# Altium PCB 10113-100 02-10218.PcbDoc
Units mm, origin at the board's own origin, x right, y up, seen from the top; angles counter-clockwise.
Board outline 67 x 67 mm, 2 copper layers (Top Layer, Bottom Layer); 24 components, 35 nets, 116 pads, 182 vias.
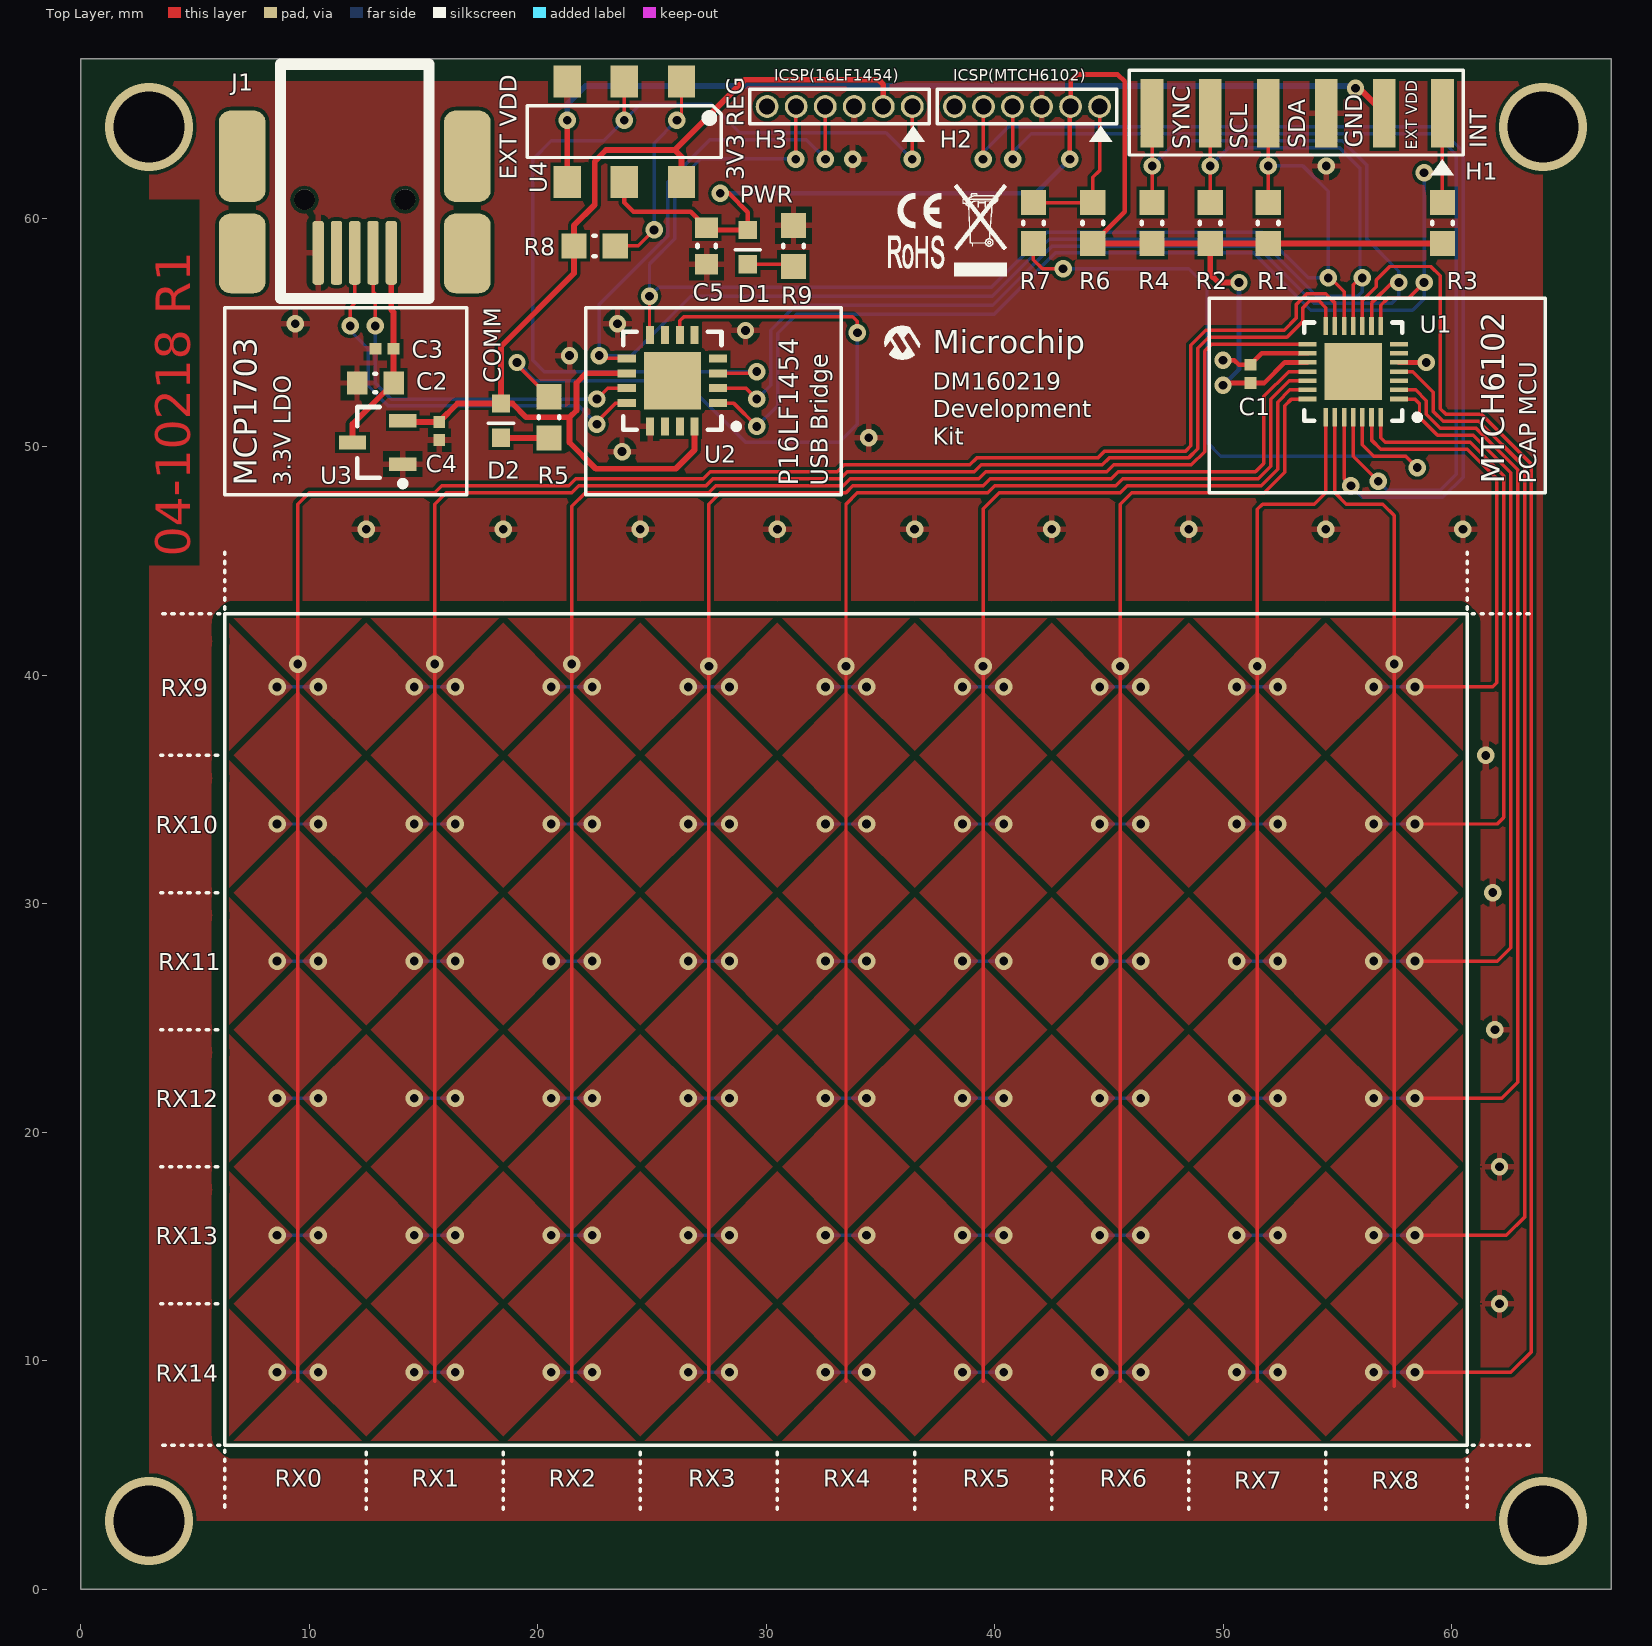
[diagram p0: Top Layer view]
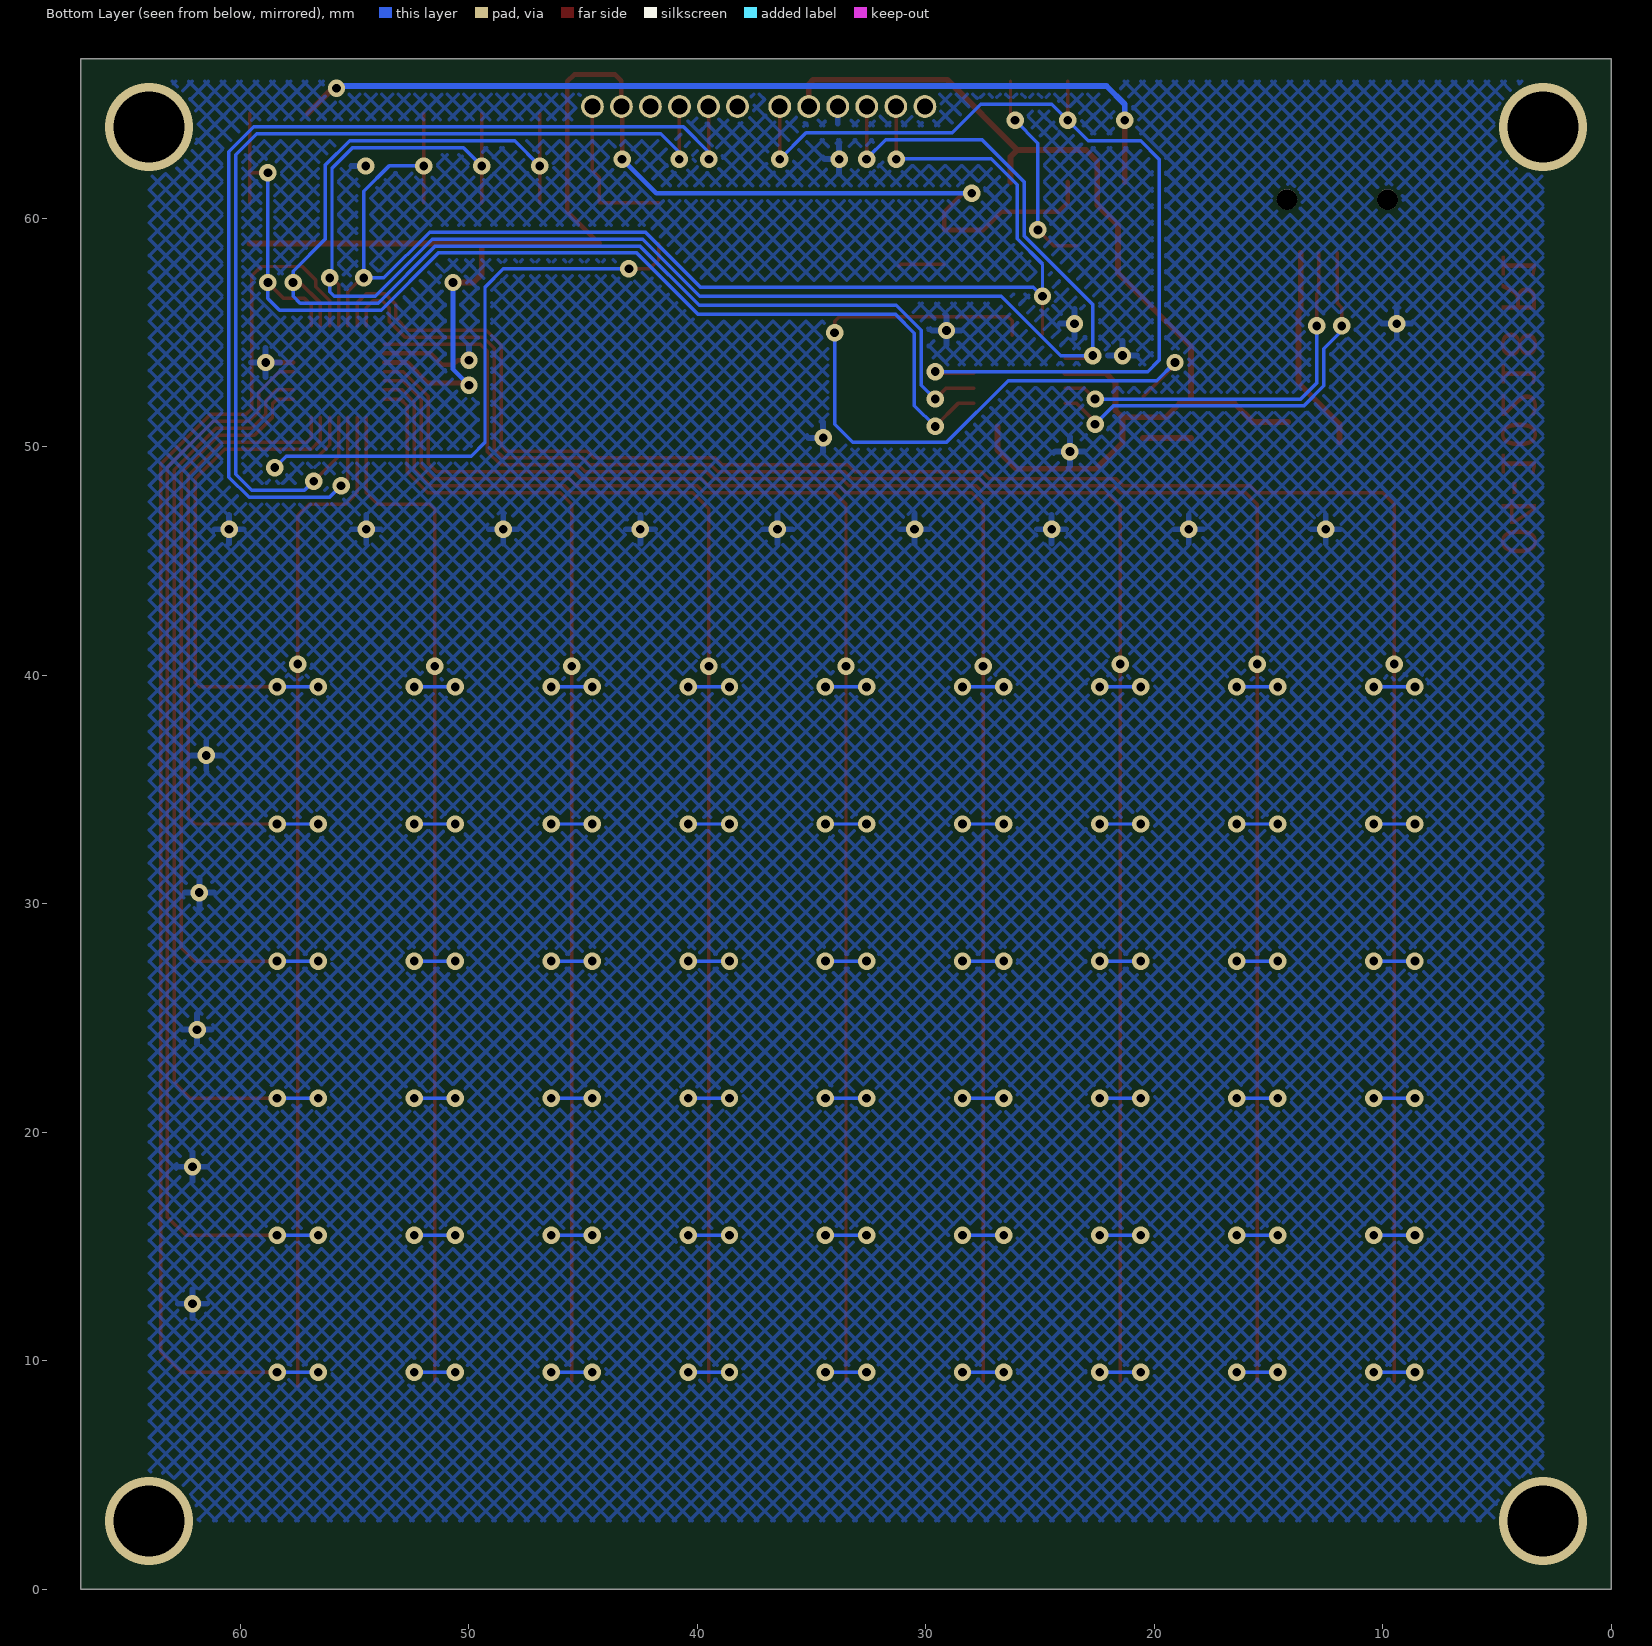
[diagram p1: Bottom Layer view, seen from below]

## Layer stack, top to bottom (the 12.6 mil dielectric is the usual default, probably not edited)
Top Solder: solder mask 0.0102, Solder Resist, Dk 3.5
Top Layer: signal copper 0.0356
Dielectric1: dielectric 0.32, FR-4, Dk 4.8
Bottom Layer: signal copper 0.0356
Bottom Solder: solder mask 0.0102, Solder Resist, Dk 3.5

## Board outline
0,0 67,0 67,67 0,67

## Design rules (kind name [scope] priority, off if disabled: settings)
Clearance "Sensor Clearance" [InPolygon AND InNet('GND') vs (INPolygon AND ((InNet('RX0') OR InNet('RX1') OR InNet('RX2') OR InNet('RX3') OR InNet('RX4') OR InNet('RX5') OR InNet('RX6') OR InNet('RX7') OR InNet('RX8') OR InNet('RX9') OR InNet('RX10') OR InNet('RX11') OR InNet('RX12') OR InNet('RX13') OR InNet('RX14'))))] p1: gap=0.768
Clearance "GND Plane Clearance" [InNet('GND')] p2: gap=0.152
Clearance [All] p3: gap=0.152
ComponentClearance [All] p1: gap=0.152 collisioncheckmode=3 verticalgap=0.254 showdistances=FALSE
HoleSize [All] p1: absolutevalues=TRUE maxlimit=3.1 minlimit=0.025 maxpercent=80.000 minpercent=20.000
HoleToHoleClearance [All] p1: gap=0.152 allowstackedmicrovias=TRUE
MinimumSolderMaskSliver [All] p1: minsoldermaskwidth=0.05
PolygonConnect PolygonConnect_1 [InNet('GND')] p1: connectstyle=Relief reliefconductorwidth=0.254 reliefentries=4 polygonreliefangle="90 Angle" airgapwidth=0.254
PolygonConnect [All] p2: connectstyle=Direct reliefconductorwidth=0.254 reliefentries=4 polygonreliefangle="90 Angle" airgapwidth=0.254
RoomDefinition "10113-100 02-10218" [InComponentClass('10113-100 02-10218')] p1: confinementstyle=ConfineOut formatcopy=TRUE lockcomponents=FALSE outline 68.5,0.4 75.4,0.4 75.4,5.8 68.5,5.8
RoutingVias [All] p1: holewidth=0.381 width=0.762 viastyle="Through Hole" minholewidth=0.381 minwidth=0.762 maxholewidth=0.762 maxwidth=1.024
SilkToSilkClearance [All] p1: silktosilkclearance=0.05
SilkToSolderMaskClearance [IsPad] p1: minsilkscreentomaskgap=0.05 clearancetoexposedcopper=TRUE
SolderMaskExpansion [All] p1: expansion=0.102
Width "Supply Width" [(InNet('3V3') OR InNet('3V3_CUSTOM') OR InNet('3V3_REG') OR InNet('5V_USB'))] p1: maxlimit=0.254 minlimit=0.152 preferedwidth=0.254
Width [All] p2: maxlimit=0.41 minlimit=0.15 preferedwidth=0.152 minimp=50.000000 maximp=50.000000 favimp=50.000000
23 further rules are at their usual default settings.

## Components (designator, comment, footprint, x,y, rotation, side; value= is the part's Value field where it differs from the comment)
C1 "CAP 100nF 25V 0402(1005)" CAPC0402(1005)60_L 51.2,53.2 r90 top
C2 "10uF" CAPC0603(1608)100_N 12.9,52.8 r0 top
C3 "CAP 100nF 25V 0402(1005)" CAPC0402(1005)60_L 13.3,54.3 r0 top
C4 "CAP 100nF 25V 0402(1005)" CAPC0402(1005)60_L 15.7,50.7 r90 top
C5 "10uF" CAPC0603(1608)100_N 27.4,58.8 r90 top
D1 "BLUE" LED_SMT-0603 29.2,59.5 r270 top
D2 "BLUE" LED_SMT-0603 18.4,51.9 r270 top
H1 "HDR-1x6" HDR-1x6_SMT 46.9,64.6 r270 top
H2 "HDR-1x6" "HDR-1x6_TH-0.05\"" 44.6,64.9 r90 top
H3 "HDR-1x6" "HDR-1x6_TH-0.05\"" 36.4,64.9 r90 top
J1 "67503-1020" MOLX-67503-1020_V 13.6,58.5 r270 top
R1 "1.8k" RESC0603(1608)_M 51.98,59.8 r270 top
R2 "1.8k" RESC0603(1608)_M 49.44,59.8 r270 top
R3 "4.7k" RESC0603(1608)_M 59.6,59.8 r270 top
R4 "4.7k" RESC0603(1608)_M 46.9,59.8 r270 top
R5 "1.8k" RESC0603(1608)_M 20.5,51.3 r270 top
R6 "20k" RESC0603(1608)_M 44.3,59.8 r90 top
R7 "100" RESC0603(1608)_M 41.7,59.8 r270 top
R8 "20k" RESC0603(1608)_M 22.5,58.8 r0 top
R9 "1.8k" RESC0603(1608)_M 31.2,58.8 r270 top
U1 "MTCH6102" MTCH6102_I/MV 55.7,53.3 r180 top
U2 "PIC16(L)F1454" PIC16LF1454_I/ML 25.9,52.9 r180 top
U3 "MCP1703T-3302E/CB" SOT-23A-CB3_L 13,50.2 r180 top
U4 "CL-SB-22B-12" CL-SB-22B-12 26.9,66.7 r180 top

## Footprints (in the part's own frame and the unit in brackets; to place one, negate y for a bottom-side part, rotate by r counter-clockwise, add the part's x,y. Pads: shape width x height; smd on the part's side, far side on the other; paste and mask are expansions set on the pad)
CAPC0402(1005)60_L [mm] "Chip Capacitor, Body 1.0x0.5mm, Height 0.6mm, IPC High Density"
  rect 0.52x0.52 smd: 1(-0.4,0) 2(0.4,0)
  body extent -0.55,-0.3 0.55,0.3, height 0.6
CAPC0603(1608)100_N [mm] "Chip Capacitor, Body 1.6x0.8mm, Height 1.0mm, IPC Medium Density"
  rect 0.9x1 smd: 1(-0.8,0) 2(0.8,0)
  silkscreen extent -0.05,-0.4 0.05,0.4, body extent -0.87,-0.48 0.88,0.47, height 1
CL-SB-22B-12 [mm]
  rect 1.2x1.4 smd: 1(0.6,0.7) 2(3.1,0.7) 3(5.6,0.7) 4(0.6,5.1) 5(3.1,5.1) 6(5.6,5.1)
  silkscreen extent -1.15,1.77 7.35,4.03
HDR-1x6_SMT [mm]
  rect 3x1 smd: 1(0,12.7) 2(0,10.16) 3(0,7.62) 4(0,5.08) 5(0,2.54) 6(0,0)
  silkscreen extent -1.89,-1.01 1.82,13.61
"HDR-1x6_TH-0.05\"" [mm]
  round 1 hole 0.7: 1(0,0) 2(0,1.27) 3(0,2.54) 4(0,3.81) 5(0,5.08) 6(0,6.35)
  silkscreen extent -0.75,-0.75 0.75,7.11
LED_SMT-0603 [mm]
  rect 0.8x0.8 smd: 1(0,0) 2(1.5,0)
  silkscreen extent 0.86,-0.55 0.86,0.55
MOLX-67503-1020_V [mm] "Mini USB Connector, SMT, Righer Angle"
  rrect50% 2.8x0.5 smd: 1(0,0) 2(0,-0.8) 3(0,-1.6) 4(0,-2.4) 5(0,-3.2)
  rrect50% 3.5x2.05 smd: 6(0.025,3.325) 8(0.025,-6.525)
  rrect50% 4x2.05 smd: 7(-4.225,3.325) 9(-4.225,-6.525)
  round 0.9 hole 0.9 unplated: X(-2.325,-3.8) Y(-2.325,0.6)
  silkscreen extent -8.25,-4.85 2,1.65, body extent -8.22,-6.56 0.78,3.34, height 3.95
MTCH6102_I/MV [mm] "Single Touch Controller"
  rect 0.8x0.2 smd: 1(-2,1.2) 2(-2,0.8) 3(-2,0.4) 4(-2,0) 5(-2,-0.4) 6(-2,-0.8) 7(-2,-1.2) 15(2,-1.2) 16(2,-0.8) 17(2,-0.4) 18(2,0) 19(2,0.4) 20(2,0.8) 21(2,1.2)
  rect 0.2x0.8 smd: 8(-1.2,-2) 9(-0.8,-2) 10(-0.4,-2) 11(0,-2) 12(0.4,-2) 13(0.8,-2) 14(1.2,-2) 22(1.2,2) 23(0.8,2) 24(0.4,2) 25(0,2) 26(-0.4,2) 27(-0.8,2) 28(-1.2,2)
  rect 2.5x2.5 smd: 29(0,0)
  silkscreen extent -2.93,-2.15 2.15,2.15, body extent -2,-2 2,2, height 1
PIC16LF1454_I/ML [mm]
  rect 0.8x0.35 smd: 1(-2,0.975) 2(-2,0.325) 3(-2,-0.325) 4(-2,-0.975) 9(2,-0.975) 10(2,-0.325) 11(2,0.325) 12(2,0.975)
  rect 0.35x0.8 smd: 5(-0.975,-2) 6(-0.325,-2) 7(0.325,-2) 8(0.975,-2) 13(0.975,2) 14(0.325,2) 15(-0.325,2) 16(-0.975,2)
  rect 2.5x2.5 smd: 17(0,0)
  silkscreen extent -2.93,-2.15 2.15,2.15, body extent -2,-2 2,2, height 1
RESC0603(1608)_M [mm] "Chip Resistor, Body 1.6x0.8mm, IPC Low Density"
  rect 1.1x1.1 smd: 1(-0.9,0) 2(0.9,0)
  silkscreen extent -0.05,-0.45 0.05,0.45, body extent -0.85,-0.47 0.85,0.47, height 0.6
SOT-23A-CB3_L [mm] "SOT346, 3-Leads, Body 2.9x1.5mm, Pitch 0.95mm, Lead Span 2.6mm, IPC High Density"
  rect 1.2x0.6 smd: 1(-1.1,0.95) 2(-1.1,-0.95) 3(1.1,0)
  silkscreen extent -1.23,-1.55 0.9,1.92, body extent -0.9,-1.55 0.9,1.55, height 1.45

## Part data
C1 C3 C4: library part CMP-1034-02073-1, "CAP 100nF 25V ±20% 0402 (1005 Metric) Thickness 0.6mm SMD"
C2 C5: library part CMP-1035-02799-1, "CAP 10uF 10V ±10% 0603 (1608 Metric) Thickness 1mm SMD"
D1 D2: library part LTST-C191KGKT, "Discrete LED"
H1 H2 H3: library part HDR-1x6_SMT, "0.1\" pitch 6-pin SMT male header"
J1: library part CMP-0411-00002-1, "USB, MINI, SMD, RA KME04-USBMU03A01"
R1 R2 R3 R4 R5 R6 R7 R8 R9: library part CMP-1012-00080-1, "1K8 0.1W 5% 0603 (1608 Metric)  SMD"
U1: "MTCH6102 Single Touch Controller"
U2: "PIC16(L)F1454 General Purpose Microcontroller"
U3: library part CMP-0136-00759-1, "250 mA, 16V, Low Quiescent Current LDO Regulator, 3-Pin SOT-23A, Extended Temperature, Tape and Reel"
U4: "Copal DPDT Slide Switch"

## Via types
v1: diameter 0.762, hole 0.381, Top Layer to Bottom Layer, 178 vias
v2: diameter 3.861, hole 3.099, Top Layer to Bottom Layer, 4 vias

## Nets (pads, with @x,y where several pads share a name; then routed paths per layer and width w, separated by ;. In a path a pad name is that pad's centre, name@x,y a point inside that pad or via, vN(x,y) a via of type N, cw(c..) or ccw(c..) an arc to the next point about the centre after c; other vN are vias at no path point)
3V3_REG: C4.2 D2.1 H3.2 R8.1 U2.10 U2.16 U3.2 U4.4 | length 49.2
  Top Layer w0.254: U3.2@14.15,51.1 C4.2 16.5,51.9 D2.1 ; U2.10 22.125,53.225 21.7,52.8 21.7,51.6 21.4,51.3 ; U4.4 26.3,62.7 26,63 ; U2.16 26.875,49.875 26.048,49.048 22.552,49.048 21.4,50.2 21.4,51.3 ; H3.2 35.13,65.87 34.93,66.07 29.07,66.07 26,63 ; D2.1 18.9,51.9 19.5,51.3 21.4,51.3 ; D2.1 18.4,54.4 21.6,57.6 R8.1 21.6,59.7 22.5,60.6 22.5,62.5 23,63 26,63
5V_USB: C2.2 C3.2 J1.1 U3.3 | length 9.1
  Top Layer w0.254: U3.3 11.9,51 C2.2 C3.2 13.7,55.9 13.6,56 J1.1
\M\C\L\R\: H3.1 U2.3 U4.2 | length 43.1
  Top Layer w0.152: v1(23.8,64.3) U4.2 ; U2.3 29.525,53.225 v1(29.6,53.3) ; v1(36.4,62.6) H3.1
  Bottom Layer w0.152: v1(29.6,53.3) 20.3,53.3 19.8,53.8 19.8,62.6 20.6,63.4 22.9,63.4 v1(23.8,64.3) 24.5,65 27.6,65 28.85,63.75 35.25,63.75 v1(36.4,62.6)
"\M\C\L\R\ EXT": R8.2 U4.1 | length 9
  Top Layer w0.152: R8.2 24.4,58.8 v1(25.1,59.5) ; v1(26.1,64.3) 26.3,64.5 U4.1
  Bottom Layer w0.152: v1(25.1,59.5) 25.1,63.3 v1(26.1,64.3)
D+: J1.3 U2.12 | length 18.7
  Top Layer w0.152: v1(11.8,55.3) 11.8,56.1 12,56.3 J1.3 ; v1(22.6,51) 22.6,51.1 23.425,51.925 U2.12
  Bottom Layer w0.152: v1(11.8,55.3) 11.8,55.096 12.596,54.3 12.596,52.674 13.474,51.796 21.804,51.796 v1(22.6,51)
D-: J1.2 U2.11 | length 17.2
  Top Layer w0.152: J1.2 12.8,56.8 12.9,56.7 v1(12.9,55.3) ; v1(22.6,52.1) 23.075,52.575 U2.11
  Bottom Layer w0.152: v1(12.9,55.3) 12.9,52.8 13.6,52.1 v1(22.6,52.1)
GND: C1.2 C2.1 C3.1 C4.1 C5.1 H1.3 H2.3 H3.3 J1.5 R9.1 U1.5 U1.16 U2.13 U3.1 U4.3 | length 5.2
  Top Layer w0.203: v1(50,53.8) 50.5,53.8 50.7,53.6 C1.2 51.7,54.1 U1.16 ; U1.5 v1(58.9,53.7)
  other v1: 62.1,12.5 62.1,18.5 61.9,24.5 61.8,30.5 61.5,36.5 12.5,46.4 18.5,46.4 24.5,46.4 30.5,46.4 36.5,46.4 42.5,46.4 48.5,46.4 54.5,46.4 60.5,46.4 23.7,49.8 34.5,50.4 21.4,54 29.1,55.1 9.4,55.4 23.5,55.4 54.52,62.3 33.8,62.6
ICSPCLK: H2.5 U1.24 | length 47.4
  Top Layer w0.152: v1(39.5,62.6) 39.5,64.88 H2.5 ; U1.24 55.3,48.6 v1(55.6,48.3)
  Bottom Layer w0.152: v1(39.5,62.6) 39.5,62.9 40.612,64.012 59.418,64.012 60.513,62.917 60.513,48.683 59.626,47.796 56.104,47.796 v1(55.6,48.3)
ICSPDAT: H2.4 U1.25 | length 43.8
  Top Layer w0.152: H2.4 40.8,64.89 v1(40.8,62.6) ; U1.25 55.7,49.6 v1(56.8,48.5)
  Bottom Layer w0.152: v1(40.8,62.6) 40.8,62.9 41.608,63.708 59.292,63.708 60.209,62.791 60.209,48.809 59.5,48.1 57.2,48.1 v1(56.8,48.5)
INT: H1.1 R3.1 U1.8 U2.1 | length 51
  Top Layer w0.152: U2.1 28.575,51.925 v1(29.6,50.9) ; U1.8 56.9,56.2 57.2,56.5 58.1,56.5 v1(58.8,57.2) ; v1(58.8,62) 59.6,62 ; R3.1 59.6,62 ; H1.1 59.6,62
  Bottom Layer w0.152: v1(29.6,50.9) 30.513,51.813 30.513,54.983 31.33,55.8 39.96,55.8 42.652,58.492 51.348,58.492 53.848,55.992 58.292,55.992 58.8,56.5 v1(58.8,57.2) v1(58.8,62)
NetD1_2: D1.2 R9.2 | length 2
  Top Layer w0.152: D1.2 31.1,58 R9.2
NetD2_2: D2.2 R5.2 | length 2.1
  Top Layer w0.254: D2.2 R5.2
NetH2_1: H2.1 R6.2 R7.1 | length 6.9
  Top Layer w0.152: R7.1 R6.2 44.3,61.8 44.6,62.1 H2.1
NetR5_1: R5.1 U2.6 | length 31.7
  Top Layer w0.152: v1@19.1,53.6 R5.1 ; U2.6 26.225,55.525 26.409,55.709 33.791,55.709 34,55.5 v1(34,55)
  Bottom Layer w0.152: v1(19.1,53.7) 19.9,52.9 26.4,52.9 29.1,50.2 33.2,50.2 34,51 v1(34,55)
R\E\S\E\T\: R7.2 U1.26 | length 29.3
  Top Layer w0.152: R7.2 41.7,58.2 42.1,57.8 v1(43,57.8) ; U1.26 56.1,50.1 56.6,49.6 58,49.6 v1(58.5,49.1)
  Bottom Layer w0.152: v1(43,57.8) 48.5,57.8 49.3,57 49.3,50.2 49.9,49.6 58,49.6 v1(58.5,49.1)
RX0: U1.13 | length 91.9
  Top Layer w0.152: 9.5,9.11 v1@9.5,40.51 ; v1@9.7,40.5 v1(9.5,40.5) 9.5,47.5 10,48 15.5,48 15.804,48.304 21.374,48.304 21.678,48.608 27.248,48.608 27.552,48.912 33.122,48.912 33.426,49.216 38.916,49.216 39.22,49.52 44.52,49.52 44.824,49.824 48.364,49.824 48.592,50.052 48.592,54.452 49.248,55.108 52.674,55.108 53.196,55.63 53.196,56.226 53.674,56.704 54.496,56.704 54.9,56.3 U1.13
RX1: U1.14 | length 85.1
  Top Layer w0.152: 15.5,9.1 v1(15.5,40.5) ; v1@15.7,40.5 v1(15.5,40.5) ; U1.14 54.5,56.1 54.2,56.4 53.8,56.4 53.5,56.1 53.5,55.504 52.8,54.804 49.374,54.804 48.896,54.326 48.896,49.926 48.49,49.52 45.02,49.52 44.716,49.216 39.416,49.216 39.112,48.912 33.552,48.912 33.248,48.608 27.678,48.608 27.374,48.304 21.804,48.304 21.5,48 16,48 15.5,47.5 v1(15.5,40.5)
RX2: U1.15 | length 76.2
  Top Layer w0.152: 21.5,9.1 v1(21.5,40.5) ; v1@21.7,40.5 v1(21.5,40.5) ; 24.2,48 22.1,48 21.5,47.4 v1(21.5,40.5) ; 24.2,48 27.5,48 27.804,48.304 33.374,48.304 33.678,48.608 39.308,48.608 39.612,48.912 44.912,48.912 45.216,49.216 48.616,49.216 49.2,49.8 49.2,54.2 49.5,54.5 U1.15
RX3: U1.18 | length 68.7
  Top Layer w0.152: 27.5,9.1 v1(27.5,40.4) 27.5,47.5 28,48 30.1,48 ; 30.1,48 33.5,48 33.804,48.304 39.504,48.304 39.808,48.608 45.108,48.608 45.412,48.912 51.422,48.912 51.788,49.278 51.788,52.218 52.87,53.3 U1.18
RX4: U1.19 | length 62.7
  Top Layer w0.152: 33.5,9.1 v1(33.5,40.4) ; v1@33.6,40.4 v1(33.5,40.4) ; U1.19 52.9,52.9 52.092,52.092 52.092,49.152 51.548,48.608 45.608,48.608 45.304,48.304 40.004,48.304 39.7,48 34,48 33.5,47.5 v1(33.5,40.4)
RX5: U1.20 | length 56.5
  Top Layer w0.152: 39.5,9.1 v1(39.5,40.4) ; v1@39.7,40.4 v1(39.5,40.4) ; U1.20 52.93,52.5 52.396,51.966 52.396,49.026 51.674,48.304 45.804,48.304 45.5,48 40.2,48 39.5,47.3 v1(39.5,40.4)
RX6: U1.21 | length 50.2
  Top Layer w0.152: 45.5,9.1 v1(45.5,40.4) 45.5,47.5 46,48 48.2,48 ; 48.2,48 51.8,48 52.7,48.9 52.7,51.8 53,52.1 U1.21
RX7: U1.22 | length 44.8
  Top Layer w0.152: 51.5,9.1 v1(51.5,40.4) 51.5,47.27 51.73,47.5 54,47.5 54.5,48 U1.22
RX8: U1.23 | length 44.1
  Top Layer w0.152: U1.23 54.9,48 55.4,47.5 57,47.5 57.5,47 v1(57.5,40.5) v1@57.4,40.5 ; 57.5,8.9 57.5,40.1
RX9: U1.27 | length 36.2
  Top Layer w0.152: U1.27 56.5,50.304 56.9,49.904 60.696,49.904 61.98,48.62 61.98,39.68 61.8,39.5 v1(58.4,39.5) v1@58.4,39.7
  Bottom Layer w0.152: v1(8.6,39.5) v1(10.4,39.5) ; v1(14.6,39.5) v1(16.4,39.5) ; v1(20.6,39.5) v1(22.4,39.5) ; v1(26.6,39.5) v1(28.4,39.5) ; v1(32.6,39.5) v1(34.4,39.5) ; v1(38.6,39.5) v1(40.4,39.5) ; v1(44.6,39.5) v1(46.4,39.5) ; v1(50.6,39.5) v1(52.4,39.5) ; v1(56.6,39.5) v1(58.4,39.5)
RX10: U1.28 | length 42.1
  Top Layer w0.152: U1.28 56.9,50.408 57.1,50.208 60.822,50.208 62.284,48.746 62.284,33.784 62,33.5 v1(58.4,33.5)
  Bottom Layer w0.152: v1(8.6,33.5) v1(10.4,33.5) ; v1(14.6,33.5) v1(16.4,33.5) ; v1(20.6,33.5) v1(22.4,33.5) ; v1(26.6,33.5) v1(28.4,33.5) ; v1(32.6,33.5) v1(34.4,33.5) ; v1(38.6,33.5) v1(40.4,33.5) ; v1(44.6,33.5) v1(46.4,33.5) ; v1(50.6,33.5) v1(52.4,33.5) ; v1(56.6,33.5) v1(58.4,33.5)
RX11: U1.1 | length 48
  Top Layer w0.152: U1.1 58.4,52.1 58.6,51.9 58.6,51.3 59.388,50.512 60.948,50.512 62.588,48.872 62.588,28.088 62,27.5 v1(58.4,27.5)
  Bottom Layer w0.152: v1(8.6,27.5) v1(10.4,27.5) ; v1(14.6,27.5) v1(16.4,27.5) ; v1(20.6,27.5) v1(22.4,27.5) ; v1(26.6,27.5) v1(28.4,27.5) ; v1(32.6,27.5) v1(34.4,27.5) ; v1(38.6,27.5) v1(40.4,27.5) ; v1(44.6,27.5) v1(46.4,27.5) ; v1(50.6,27.5) v1(52.4,27.5) ; v1(56.6,27.5) v1(58.4,27.5)
RX12: U1.2 | length 54.8
  Top Layer w0.152: U1.2 58.43,52.5 58.904,52.026 58.904,51.426 59.514,50.816 61.074,50.816 62.892,48.998 62.892,22.192 62.2,21.5 v1(58.4,21.5)
  Bottom Layer w0.152: v1(8.6,21.5) v1(10.4,21.5) ; v1(14.6,21.5) v1(16.4,21.5) ; v1(20.6,21.5) v1(22.4,21.5) ; v1(26.6,21.5) v1(28.4,21.5) ; v1(32.6,21.5) v1(34.4,21.5) ; v1(38.6,21.5) v1(40.4,21.5) ; v1(44.6,21.5) v1(46.4,21.5) ; v1(50.6,21.5) v1(52.4,21.5) ; v1(56.6,21.5) v1(58.4,21.5)
RX13: U1.4 | length 61.9
  Top Layer w0.152: U1.4 58.3,53.3 59.208,52.392 59.208,51.552 59.64,51.12 61.2,51.12 63.196,49.124 63.196,16.296 62.4,15.5 v1(58.4,15.5)
  Bottom Layer w0.152: v1(8.6,15.5) v1(10.4,15.5) ; v1(14.6,15.5) v1(16.4,15.5) ; v1(20.6,15.5) v1(22.4,15.5) ; v1(26.6,15.5) v1(28.4,15.5) ; v1(32.6,15.5) v1(34.4,15.5) ; v1(38.6,15.5) v1(40.4,15.5) ; v1(44.6,15.5) v1(46.4,15.5) ; v1(50.6,15.5) v1(52.4,15.5) ; v1(56.6,15.5) v1(58.4,15.5)
RX14: U1.10 | length 76.8
  Top Layer w0.152: U1.10 56.1,56.4 56.709,57.009 56.709,57.309 57.3,57.9 59.1,57.9 59.512,57.488 59.512,51.678 59.766,51.424 61.326,51.424 63.5,49.25 63.5,10.4 62.6,9.5 v1(58.4,9.5)
  Bottom Layer w0.152: v1(8.6,9.5) v1(10.4,9.5) ; v1(14.6,9.5) v1(16.4,9.5) ; v1(20.6,9.5) v1(22.4,9.5) ; v1(26.6,9.5) v1(28.4,9.5) ; v1(32.6,9.5) v1(34.4,9.5) ; v1(38.6,9.5) v1(40.4,9.5) ; v1(44.6,9.5) v1(46.4,9.5) ; v1(50.6,9.5) v1(52.4,9.5) ; v1(56.6,9.5) v1(58.4,9.5)
SCL: H1.5 H3.4 R2.1 U1.11 U2.9 | length 75.9
  Top Layer w0.152: v1(22.7,54) 22.825,53.875 U2.9 ; v1(32.6,62.6) H3.4@32.6,64.85 ; R2.1 v1(49.44,62.3) H1.5 ; U1.11 55.7,57.1 56,57.4 v1(56.1,57.4)
  Bottom Layer w0.152: v1@32.58,62.63 31.764,63.446 27.546,63.446 25.709,61.609 25.709,59.248 22.7,56.239 v1(22.7,54) 24.1,54 26.7,56.6 39.9,56.6 42.4,59.1 51.6,59.1 54.1,56.6 55.9,56.6 56.1,56.8 v1(56.1,57.4) 55.996,57.504 55.996,62.204 55.9,62.3 55.1,63.1 50.24,63.1 v1(49.44,62.3)
SDA: H1.4 H3.5 R1.1 U1.12 U2.8 | length 59.9
  Top Layer w0.152: U2.8@24.9,54.925 v1(24.9,56.6) ; H3.5@31.3,64.88 v1(31.3,62.6) v1@31.32,62.62 ; R1.1 v1(51.98,62.3) H1.4 ; v1@54.7,57.4 55.3,56.8 U1.12
  Bottom Layer w0.152: v1@31.3,62.61 27.14,62.61 26.013,61.483 26.013,59.122 24.9,58.009 v1(24.9,56.6) 25.3,57 39.87,57 42.274,59.404 51.726,59.404 53.73,57.4 v1(54.6,57.4) 54.6,61.2 53.5,62.3 v1(51.98,62.3)
SYNC: H1.6 R4.1 U1.9 U2.2 | length 58.4
  Top Layer w0.152: U2.2 29.125,52.575 v1(29.6,52.1) ; R4.1 v1(46.9,62.3) H1.6 ; U1.9 56.5,56.3 57.4,57.2 v1(57.7,57.2)
  Bottom Layer w0.152: v1(29.6,52.1) 30.209,52.709 30.209,55.109 31.3,56.2 39.93,56.2 42.526,58.796 51.474,58.796 53.974,56.296 57.396,56.296 57.7,56.6 v1(57.7,57.2) 57.7,57.7 56.3,59.1 56.3,62.33 55.226,63.404 48.004,63.404 v1(46.9,62.3)
VDD: C1.1 C5.2 D1.1 H2.2 R1.2 R2.2 R3.2 R4.2 R6.1 U1.17 U4.5 | length 65.7
  Top Layer w0.203: U4.5 23.8,60.7 24.2,60.3 26.7,60.3 C5.2 27.5,59.5 D1.1 29.2,60.28 28.38,61.1 v1(28,61.1) ; v1(43.3,62.6) 43.3,64.87 H2.2 43.33,66.03 43.6,66.3 45.4,66.3 45.7,66 45.7,60.3 R6.1 ; v1(50,52.7) 50.1,52.8 C1.1 51.8,52.8 52.7,53.7 U1.17
  Top Layer w0.254: R6.1 R4.2 R2.2 ; v1(50.7,57.2) 49.8,57.2 49.44,57.56 R2.2 ; R3.2 R1.2 R2.2
  Bottom Layer w0.203: v1(28,61.1) 41.8,61.1 v1(43.3,62.6) ; v1(50,52.7) 50.7,53.4 v1(50.7,57.2)
VDD_CUSTOM: H1.2 U4.6 | length 40
  Top Layer w0.254: U4.6 v1(21.3,64.3) ; v1(55.8,65.7) 55.96,65.7 H1.2
  Bottom Layer w0.254: v1(21.3,64.3) 21.3,65 22.1,65.8 55.7,65.8 v1(55.8,65.7)
pads on no net: H2.6 H3.6 J1.4 J1.6 J1.7 J1.8 J1.9 J1.X J1.Y U1.3 U1.6 U1.7 U1.29 U2.4 U2.5 U2.7 U2.14 U2.15 U2.17
copper on no net:
  other v2: 3,3 64,3 3,64 64,64

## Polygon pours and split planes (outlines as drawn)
GND on Top Layer "GND2" (solid, pour order 130): 60.7,21.5 63.3,21.5 63.3,39.396 63.196,39.5 60.7,39.5
RX8 on Top Layer "RX8" (solid, pour order 127): 54.7,12.5 57.5,9.7 60.3,12.5 57.5,15.3
RX8 on Top Layer "RX8" (solid, pour order 223): 54.7,6.5 60.3,6.5 57.5,9.3
RX14 on Top Layer "RX14" (solid, pour order 224): 6.5,12.3 6.5,6.7 9.3,9.5
RX8 on Top Layer "RX8" (solid, pour order 128): 54.7,18.5 57.5,15.7 60.3,18.5 57.5,21.3
RX8 on Top Layer "RX8" (solid, pour order 129): 54.7,24.5 57.5,21.7 60.3,24.5 57.5,27.3
RX8 on Top Layer "RX8" (solid, pour order 131): 54.7,30.5 57.5,27.7 60.3,30.5 57.5,33.3
RX8 on Top Layer "RX8" (solid, pour order 132): 54.7,36.5 57.5,33.7 60.3,36.5 57.5,39.3
RX8 on Top Layer "RX8" (solid, pour order 225): 60.3,42.5 54.7,42.5 57.5,39.7
RX7 on Top Layer "RX7" (solid, pour order 226): 54.3,42.5 48.7,42.5 51.5,39.7
RX7 on Top Layer "RX7" (solid, pour order 133): 48.7,36.5 51.5,33.7 54.3,36.5 51.5,39.3
RX7 on Top Layer "RX7" (solid, pour order 134): 48.7,30.5 51.5,27.7 54.3,30.5 51.5,33.3
RX7 on Top Layer "RX7" (solid, pour order 135): 48.7,24.5 51.5,21.7 54.3,24.5 51.5,27.3
RX7 on Top Layer "RX7" (solid, pour order 136): 48.7,18.5 51.5,15.7 54.3,18.5 51.5,21.3
RX7 on Top Layer "RX7" (solid, pour order 227): 48.7,6.5 54.3,6.5 51.5,9.3
RX7 on Top Layer "RX7" (solid, pour order 137): 48.7,12.5 51.5,9.7 54.3,12.5 51.5,15.3
RX6 on Top Layer "RX6" (solid, pour order 228): 48.3,42.5 42.7,42.5 45.5,39.7
RX6 on Top Layer "RX6" (solid, pour order 138): 42.7,36.5 45.5,33.7 48.3,36.5 45.5,39.3
RX6 on Top Layer "RX6" (solid, pour order 139): 42.7,30.5 45.5,27.7 48.3,30.5 45.5,33.3
RX6 on Top Layer "RX6" (solid, pour order 140): 42.7,24.5 45.5,21.7 48.3,24.5 45.5,27.3
RX6 on Top Layer "RX6" (solid, pour order 141): 42.7,18.5 45.5,15.7 48.3,18.5 45.5,21.3
RX6 on Top Layer "RX6" (solid, pour order 229): 42.7,6.5 48.3,6.5 45.5,9.3
RX6 on Top Layer "RX6" (solid, pour order 142): 42.7,12.5 45.5,9.7 48.3,12.5 45.5,15.3
RX5 on Top Layer "RX5" (solid, pour order 230): 42.3,42.5 36.7,42.5 39.5,39.7
RX5 on Top Layer "RX5" (solid, pour order 143): 36.7,36.5 39.5,33.7 42.3,36.5 39.5,39.3
RX5 on Top Layer "RX5" (solid, pour order 144): 36.7,30.5 39.5,27.7 42.3,30.5 39.5,33.3
RX5 on Top Layer "RX5" (solid, pour order 145): 36.7,24.5 39.5,21.7 42.3,24.5 39.5,27.3
RX5 on Top Layer "RX5" (solid, pour order 146): 36.7,18.5 39.5,15.7 42.3,18.5 39.5,21.3
RX5 on Top Layer "RX5" (solid, pour order 231): 36.7,6.5 42.3,6.5 39.5,9.3
RX5 on Top Layer "RX5" (solid, pour order 148): 36.7,12.5 39.5,9.7 42.3,12.5 39.5,15.3
RX4 on Top Layer "RX4" (solid, pour order 232): 36.3,42.5 30.7,42.5 33.5,39.7
RX4 on Top Layer "RX4" (solid, pour order 149): 30.7,36.5 33.5,33.7 36.3,36.5 33.5,39.3
RX4 on Top Layer "RX4" (solid, pour order 151): 30.7,30.5 33.5,27.7 36.3,30.5 33.5,33.3
RX4 on Top Layer "RX4" (solid, pour order 152): 30.7,24.5 33.5,21.7 36.3,24.5 33.5,27.3
RX4 on Top Layer "RX4" (solid, pour order 153): 30.7,18.5 33.5,15.7 36.3,18.5 33.5,21.3
RX4 on Top Layer "RX4" (solid, pour order 233): 30.7,6.5 36.3,6.5 33.5,9.3
RX4 on Top Layer "RX4" (solid, pour order 154): 30.7,12.5 33.5,9.7 36.3,12.5 33.5,15.3
RX3 on Top Layer "RX3" (solid, pour order 234): 30.3,42.5 24.7,42.5 27.5,39.7
RX3 on Top Layer "RX3" (solid, pour order 155): 24.7,36.5 27.5,33.7 30.3,36.5 27.5,39.3
RX3 on Top Layer "RX3" (solid, pour order 156): 24.7,30.5 27.5,27.7 30.3,30.5 27.5,33.3
RX3 on Top Layer "RX3" (solid, pour order 157): 24.7,24.5 27.5,21.7 30.3,24.5 27.5,27.3
RX3 on Top Layer "RX3" (solid, pour order 158): 24.7,18.5 27.5,15.7 30.3,18.5 27.5,21.3
RX3 on Top Layer "RX3" (solid, pour order 235): 24.7,6.5 30.3,6.5 27.5,9.3
RX3 on Top Layer "RX3" (solid, pour order 159): 24.7,12.5 27.5,9.7 30.3,12.5 27.5,15.3
RX2 on Top Layer "RX2" (solid, pour order 236): 24.3,42.5 18.7,42.5 21.5,39.7
RX2 on Top Layer "RX2" (solid, pour order 160): 18.7,36.5 21.5,33.7 24.3,36.5 21.5,39.3
RX2 on Top Layer "RX2" (solid, pour order 161): 18.7,30.5 21.5,27.7 24.3,30.5 21.5,33.3
RX2 on Top Layer "RX2" (solid, pour order 162): 18.7,24.5 21.5,21.7 24.3,24.5 21.5,27.3
RX2 on Top Layer "RX2" (solid, pour order 163): 18.7,18.5 21.5,15.7 24.3,18.5 21.5,21.3
RX2 on Top Layer "RX2" (solid, pour order 237): 18.7,6.5 24.3,6.5 21.5,9.3
RX2 on Top Layer "RX2" (solid, pour order 164): 18.7,12.5 21.5,9.7 24.3,12.5 21.5,15.3
RX1 on Top Layer "RX1" (solid, pour order 238): 18.3,42.5 12.7,42.5 15.5,39.7
RX1 on Top Layer "RX1" (solid, pour order 165): 12.7,36.5 15.5,33.7 18.3,36.5 15.5,39.3
RX1 on Top Layer "RX1" (solid, pour order 166): 12.7,30.5 15.5,27.7 18.3,30.5 15.5,33.3
RX1 on Top Layer "RX1" (solid, pour order 167): 12.7,24.5 15.5,21.7 18.3,24.5 15.5,27.3
RX1 on Top Layer "RX1" (solid, pour order 168): 12.7,18.5 15.5,15.7 18.3,18.5 15.5,21.3
RX1 on Top Layer "RX1" (solid, pour order 239): 12.7,6.5 18.3,6.5 15.5,9.3
RX1 on Top Layer "RX1" (solid, pour order 169): 12.7,12.5 15.5,9.7 18.3,12.5 15.5,15.3
RX0 on Top Layer "RX0" (solid, pour order 240): 12.3,42.5 6.7,42.5 9.5,39.7
RX0 on Top Layer "RX0" (solid, pour order 170): 6.7,36.5 9.5,33.7 12.3,36.5 9.5,39.3
RX0 on Top Layer "RX0" (solid, pour order 171): 6.7,30.5 9.5,27.7 12.3,30.5 9.5,33.3
RX0 on Top Layer "RX0" (solid, pour order 172): 6.7,24.5 9.5,21.7 12.3,24.5 9.5,27.3
RX0 on Top Layer "RX0" (solid, pour order 173): 6.7,18.5 9.5,15.7 12.3,18.5 9.5,21.3
RX0 on Top Layer "RX0" (solid, pour order 241): 6.7,6.5 12.3,6.5 9.5,9.3
RX0 on Top Layer "RX0" (solid, pour order 174): 6.7,12.5 9.5,9.7 12.3,12.5 9.5,15.3
RX14 on Top Layer "RX14" (solid, pour order 175): 12.5,12.3 9.7,9.5 12.5,6.7 15.3,9.5
RX14 on Top Layer "RX14" (solid, pour order 176): 18.5,12.3 15.7,9.5 18.5,6.7 21.3,9.5
RX14 on Top Layer "RX14" (solid, pour order 177): 24.5,12.3 21.7,9.5 24.5,6.7 27.3,9.5
RX14 on Top Layer "RX14" (solid, pour order 178): 30.5,12.3 27.7,9.5 30.5,6.7 33.3,9.5
RX14 on Top Layer "RX14" (solid, pour order 179): 36.5,12.3 33.7,9.5 36.5,6.7 39.3,9.5
RX14 on Top Layer "RX14" (solid, pour order 180): 42.5,12.3 39.7,9.5 42.5,6.7 45.3,9.5
RX14 on Top Layer "RX14" (solid, pour order 181): 48.5,12.3 45.7,9.5 48.5,6.7 51.3,9.5
RX14 on Top Layer "RX14" (solid, pour order 182): 54.5,12.3 51.7,9.5 54.5,6.7 57.3,9.5
RX14 on Top Layer "RX14" (solid, pour order 242): 60.5,6.7 60.5,12.3 57.7,9.5
RX13 on Top Layer "RX13" (solid, pour order 243): 60.5,12.7 60.5,18.3 57.7,15.5
RX13 on Top Layer "RX13" (solid, pour order 183): 54.5,18.3 51.7,15.5 54.5,12.7 57.3,15.5
RX13 on Top Layer "RX13" (solid, pour order 184): 48.5,18.3 45.7,15.5 48.5,12.7 51.3,15.5
RX13 on Top Layer "RX13" (solid, pour order 185): 42.5,18.3 39.7,15.5 42.5,12.7 45.3,15.5
RX13 on Top Layer "RX13" (solid, pour order 186): 36.5,18.3 33.7,15.5 36.5,12.7 39.3,15.5
RX13 on Top Layer "RX13" (solid, pour order 187): 30.5,18.3 27.7,15.5 30.5,12.7 33.3,15.5
RX13 on Top Layer "RX13" (solid, pour order 188): 24.5,18.3 21.7,15.5 24.5,12.7 27.3,15.5
RX13 on Top Layer "RX13" (solid, pour order 189): 18.5,18.3 15.7,15.5 18.5,12.7 21.3,15.5
RX13 on Top Layer "RX13" (solid, pour order 190): 12.5,18.3 9.7,15.5 12.5,12.7 15.3,15.5
RX13 on Top Layer "RX13" (solid, pour order 244): 6.5,18.3 6.5,12.7 9.3,15.5
RX12 on Top Layer "RX12" (solid, pour order 245): 60.5,18.7 60.5,24.3 57.7,21.5
RX12 on Top Layer "RX12" (solid, pour order 191): 54.5,24.3 51.7,21.5 54.5,18.7 57.3,21.5
RX12 on Top Layer "RX12" (solid, pour order 192): 48.5,24.3 45.7,21.5 48.5,18.7 51.3,21.5
RX12 on Top Layer "RX12" (solid, pour order 193): 42.5,24.3 39.7,21.5 42.5,18.7 45.3,21.5
RX12 on Top Layer "RX12" (solid, pour order 194): 36.5,24.3 33.7,21.5 36.5,18.7 39.3,21.5
RX12 on Top Layer "RX12" (solid, pour order 195): 30.5,24.3 27.7,21.5 30.5,18.7 33.3,21.5
RX12 on Top Layer "RX12" (solid, pour order 196): 24.5,24.3 21.7,21.5 24.5,18.7 27.3,21.5
RX12 on Top Layer "RX12" (solid, pour order 197): 18.5,24.3 15.7,21.5 18.5,18.7 21.3,21.5
RX12 on Top Layer "RX12" (solid, pour order 198): 12.5,24.3 9.7,21.5 12.5,18.7 15.3,21.5
RX12 on Top Layer "RX12" (solid, pour order 246): 6.5,24.3 6.5,18.7 9.3,21.5
RX11 on Top Layer "RX11" (solid, pour order 247): 60.5,24.7 60.5,30.3 57.7,27.5
RX11 on Top Layer "RX11" (solid, pour order 199): 54.5,30.3 51.7,27.5 54.5,24.7 57.3,27.5
RX11 on Top Layer "RX11" (solid, pour order 200): 48.5,30.3 45.7,27.5 48.5,24.7 51.3,27.5
RX11 on Top Layer "RX11" (solid, pour order 201): 42.5,30.3 39.7,27.5 42.5,24.7 45.3,27.5
RX11 on Top Layer "RX11" (solid, pour order 202): 36.5,30.3 33.7,27.5 36.5,24.7 39.3,27.5
RX11 on Top Layer "RX11" (solid, pour order 203): 30.5,30.3 27.7,27.5 30.5,24.7 33.3,27.5
RX11 on Top Layer "RX11" (solid, pour order 204): 24.5,30.3 21.7,27.5 24.5,24.7 27.3,27.5
RX11 on Top Layer "RX11" (solid, pour order 205): 18.5,30.3 15.7,27.5 18.5,24.7 21.3,27.5
RX11 on Top Layer "RX11" (solid, pour order 206): 12.5,30.3 9.7,27.5 12.5,24.7 15.3,27.5
RX11 on Top Layer "RX11" (solid, pour order 248): 6.5,30.3 6.5,24.7 9.3,27.5
RX10 on Top Layer "RX10" (solid, pour order 249): 60.5,30.7 60.5,36.3 57.7,33.5
RX10 on Top Layer "RX10" (solid, pour order 207): 54.5,36.3 51.7,33.5 54.5,30.7 57.3,33.5
RX10 on Top Layer "RX10" (solid, pour order 208): 48.5,36.3 45.7,33.5 48.5,30.7 51.3,33.5
RX10 on Top Layer "RX10" (solid, pour order 209): 42.5,36.3 39.7,33.5 42.5,30.7 45.3,33.5
RX10 on Top Layer "RX10" (solid, pour order 210): 36.5,36.3 33.7,33.5 36.5,30.7 39.3,33.5
RX10 on Top Layer "RX10" (solid, pour order 211): 30.5,36.3 27.7,33.5 30.5,30.7 33.3,33.5
RX10 on Top Layer "RX10" (solid, pour order 212): 24.5,36.3 21.7,33.5 24.5,30.7 27.3,33.5
RX10 on Top Layer "RX10" (solid, pour order 213): 18.5,36.3 15.7,33.5 18.5,30.7 21.3,33.5
RX10 on Top Layer "RX10" (solid, pour order 214): 12.5,36.3 9.7,33.5 12.5,30.7 15.3,33.5
RX10 on Top Layer "RX10" (solid, pour order 250): 6.5,36.3 6.5,30.7 9.3,33.5
RX9 on Top Layer "RX9" (solid, pour order 251): 60.5,36.7 60.5,42.3 57.7,39.5
RX9 on Top Layer "RX9" (solid, pour order 215): 54.5,42.3 51.7,39.5 54.5,36.7 57.3,39.5
RX9 on Top Layer "RX9" (solid, pour order 216): 48.5,42.3 45.7,39.5 48.5,36.7 51.3,39.5
RX9 on Top Layer "RX9" (solid, pour order 217): 42.5,42.3 39.7,39.5 42.5,36.7 45.3,39.5
RX9 on Top Layer "RX9" (solid, pour order 218): 36.5,42.3 33.7,39.5 36.5,36.7 39.3,39.5
RX9 on Top Layer "RX9" (solid, pour order 219): 30.5,42.3 27.7,39.5 30.5,36.7 33.3,39.5
RX9 on Top Layer "RX9" (solid, pour order 220): 24.5,42.3 21.7,39.5 24.5,36.7 27.3,39.5
RX9 on Top Layer "RX9" (solid, pour order 221): 18.5,42.3 15.7,39.5 18.5,36.7 21.3,39.5
RX9 on Top Layer "RX9" (solid, pour order 222): 12.5,42.3 9.7,39.5 12.5,36.7 15.3,39.5
RX9 on Top Layer "RX9" (solid, pour order 252): 6.5,42.3 6.5,36.7 9.3,39.5
GND on Top Layer "GND Fill" (solid, remove dead copper, pour order 150): 3,3 64,3 64,66 3,66
GND on Bottom Layer "GND Fill" (hatched 45Degree grid 0.508 track 0.152, remove dead copper, pour order 147): 3,3 64,3 64,66 3,66

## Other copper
Top Layer:
  text "04-10218 R1" at 4.8,45.2 h1.52 r90

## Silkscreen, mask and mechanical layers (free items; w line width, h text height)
Top Overlay:
  drawing of 4452 lines, arcs and shapes, not listed
  text "ICSP(16LF1454)" at 30.36,66.04 h0.5
  text "ICSP(MTCH6102)" at 38.19,66.04 h0.5
  text "GND" at 56.1,63.1 h0.75 r90
  text "SDA" at 53.61,63.07 h0.75 r90
  text "INT" at 61.55,63.07 h0.75 r90
  text "SCL" at 51.06,63.05 h0.75 r90
  text "SYNC" at 48.55,63.03 h0.75 r90
  text "EXT VDD" at 58.5,63 h0.5 r90
  text "EXT VDD" at 19.1,61.7 h0.75 r90
  text "3V3 REG" at 29.03,61.67 h0.75 r90
  text "PWR" at 28.84,60.69 h0.75
  text "Microchip" at 37.3,54.1 h1
  text "COMM" at 18.4,52.8 h0.75 r90
  text "DM160219" at 37.3,52.5 h0.75
  text "Development" at 37.3,51.3 h0.75
  text "Kit" at 37.3,50.1 h0.75
  text "MTCH6102" at 62.3,48.4 h1 r90
  text "PCAP MCU" at 63.7,48.4 h0.75 r90
  text "MCP1703" at 7.7,48.3 h1 r90
  text "3.3V LDO" at 9.2,48.3 h0.75 r90
  text "P16LF1454" at 31.4,48.304 h0.85 r90
  text "USB Bridge" at 32.7,48.3 h0.75 r90
  text "RX9" at 3.5,39.1 h0.75
  text "RX10" at 3.3,33.1 h0.75
  text "RX11" at 3.4,27.1 h0.75
  text "RX12" at 3.3,21.1 h0.75
  text "RX13" at 3.3,15.1 h0.75
  text "RX14" at 3.3,9.1 h0.75
  text "RX0" at 8.5,4.5 h0.75
  text "RX1" at 14.5,4.5 h0.75
  text "RX2" at 20.5,4.5 h0.75
  text "RX3" at 26.6,4.5 h0.75
  text "RX4" at 32.5,4.5 h0.75
  text "RX5" at 38.6,4.5 h0.75
  text "RX6" at 44.6,4.5 h0.75
  text "RX7" at 50.5,4.4 h0.75
  text "RX8" at 56.5,4.4 h0.75
Mechanical 1:
  the board outline again, w0.254
Drill Drawing:
  circle w0.025: c80.355,52.988 r0.635
  lines w0.025: 79.72,40.923 80.99,40.923 80.99,42.193 79.72,42.193 79.72,40.923 ; 79.72,45.05 80.038,45.05 80.355,44.733 80.673,45.05 80.99,45.05 80.673,45.368 80.99,45.685 80.673,45.685 80.355,46.003 80.038,45.685 79.72,45.685 80.038,45.368 79.72,45.05 ; 79.72,49.813 80.99,49.813 80.355,48.543 79.72,49.813
  lines w0.381: 77.99,39.78 176.516,39.78 ; 77.99,55.02 176.516,55.02 ; 91.982,35.97 91.982,58.83 ; 109.707,35.97 109.707,58.83 ; 143.885,35.97 143.885,58.83 ; 156.734,35.97 156.734,58.83 ; 77.99,35.97 176.516,35.97 176.516,58.83 77.99,58.83 77.99,35.97
  text "Symbol" at 80.276,56.163 h1.83
  text "Hit Count" at 93.125,56.163 h1.83
  text "Finished Hole Size" at 110.85,56.163 h1.83
  text "Plated" at 145.028,56.163 h1.83
  text "Hole Type" at 157.877,56.163 h1.83
  text "2" at 93.125,52.353 h1.52
  text "35.43mil (0.900mm)" at 110.85,52.353 h1.52
  text "NPTH" at 145.028,52.353 h1.52
  text "Round" at 157.877,52.353 h1.52
  text "4" at 93.125,48.543 h1.52
  text "122.00mil (3.099mm)" at 110.85,48.543 h1.52
  text "PTH" at 145.028,48.543 h1.52
  text "Round" at 157.877,48.543 h1.52
  text "12" at 93.125,44.733 h1.52
  text "27.56mil (0.700mm)" at 110.85,44.733 h1.52
  text "PTH" at 145.028,44.733 h1.52
  text "Round" at 157.877,44.733 h1.52
  text "178" at 93.125,40.923 h1.52
  text "15.00mil (0.381mm)" at 110.85,40.923 h1.52
  text "PTH" at 145.028,40.923 h1.52
  text "Round" at 157.877,40.923 h1.52
  text "196 Total" at 93.125,37.113 h1.52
